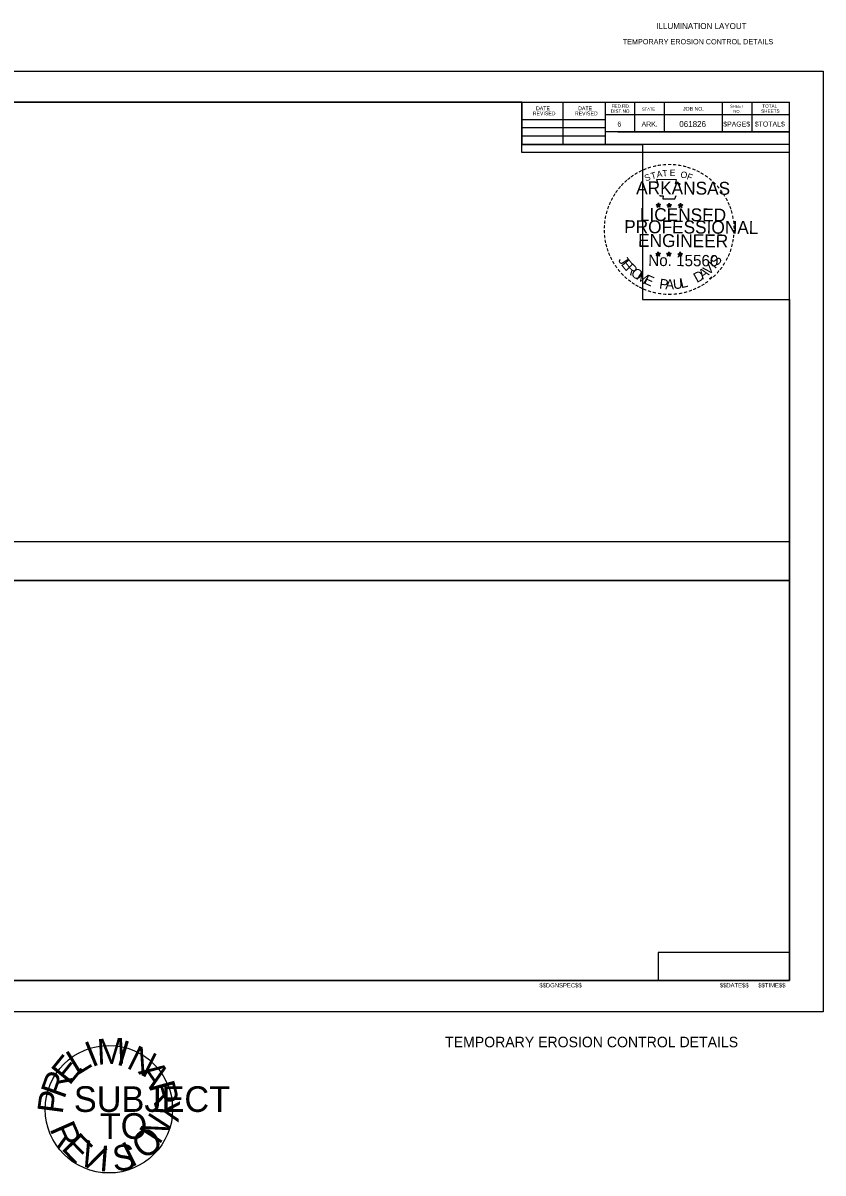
# Model space of a CAD drawing. Extents: x -1.6 to 32.4, y -4.5 to 22.4.
# Drawn here: x 13.68 to 32.4, y -4.5 to 22.4 of the extents above; entities that cross this region are included whole.
import ezdxf

# ---------------------------------------------------------------- set-up
doc = ezdxf.new("R2010")
doc.units = 0
for name, color, linetype in [('Level 1', 7, 'Continuous'), ('Level 37', 7, 'Continuous'), ('Level 48', 7, 'Continuous'), ('Level 49', 7, 'Continuous'), ('Level 63', 7, 'Continuous'), ('R_Border Prelim', 7, 'Continuous'), ('R_No Plot', 7, 'Continuous'), ('TYPICAL FONT', 7, 'Continuous')]:
    doc.layers.add(name, color=color, linetype=linetype)

# ---------------------------------------------------------------- blocks, each defined once
blk = doc.blocks.new('JDAVISAR')
at = {"layer": 'Level 49'}
for p, q in [((-0.129, 0.302), (-0.133, 0.28)), ((-0.129, 0.302), (-0.133, 0.282)), ((-0.129, 0.302), (-0.131, 0.282)), ((-0.129, 0.271), (-0.129, 0.302)), ((-0.129, 0.302), (-0.124, 0.28)), ((-0.129, 0.302), (-0.125, 0.282)), ((-0.129, 0.302), (-0.128, 0.282)), ((0.006, 0.3), (0.002, 0.279)), ((0.006, 0.3), (0.002, 0.28)), ((0.006, 0.3), (0.003, 0.28)), ((0.006, 0.271), (0.006, 0.3)), ((0.006, 0.3), (0.011, 0.279)), ((0.006, 0.3), (0.01, 0.28)), ((0.006, 0.3), (0.007, 0.28)), ((0.149, 0.298), (0.144, 0.279)), ((0.149, 0.298), (0.147, 0.278)), ((0.149, 0.298), (0.147, 0.278)), ((0.149, 0.268), (0.149, 0.298)), ((0.149, 0.298), (0.155, 0.278)), ((0.149, 0.298), (0.153, 0.278)), ((0.149, 0.298), (0.151, 0.278)), ((-0.158, 0.28), (-0.129, 0.271)), ((-0.158, 0.28), (-0.137, 0.279)), ((-0.158, 0.28), (-0.137, 0.278)), ((-0.158, 0.28), (-0.139, 0.275)), ((-0.158, 0.28), (-0.139, 0.272)), ((-0.158, 0.28), (-0.139, 0.271)), ((-0.158, 0.28), (-0.139, 0.268)), ((-0.146, 0.247), (-0.129, 0.271)), ((-0.146, 0.247), (-0.139, 0.27)), ((-0.146, 0.247), (-0.137, 0.267)), ((-0.146, 0.247), (-0.136, 0.266)), ((-0.146, 0.247), (-0.133, 0.264)), ((-0.146, 0.247), (-0.129, 0.264)), ((-0.146, 0.247), (-0.129, 0.262)), ((-0.101, 0.28), (-0.129, 0.271)), ((-0.112, 0.246), (-0.129, 0.271)), ((-0.112, 0.246), (-0.129, 0.264)), ((-0.112, 0.246), (-0.129, 0.262)), ((-0.101, 0.28), (-0.127, 0.278)), ((-0.112, 0.246), (-0.127, 0.264)), ((-0.101, 0.28), (-0.124, 0.276)), ((-0.101, 0.28), (-0.124, 0.274)), ((-0.112, 0.246), (-0.124, 0.27)), ((-0.112, 0.246), (-0.124, 0.267)), ((-0.112, 0.246), (-0.121, 0.271)), ((-0.101, 0.28), (-0.12, 0.274)), ((-0.101, 0.28), (-0.117, 0.272)), ((-0.101, 0.28), (-0.116, 0.271)), ((-0.023, 0.279), (0.006, 0.271)), ((-0.023, 0.279), (-0.002, 0.278)), ((-0.023, 0.279), (-0.002, 0.276)), ((-0.023, 0.279), (-0.002, 0.275)), ((-0.023, 0.279), (-0.003, 0.271)), ((-0.023, 0.279), (-0.003, 0.27)), ((-0.023, 0.279), (-0.003, 0.267)), ((-0.011, 0.246), (0.006, 0.271)), ((-0.011, 0.246), (-0.002, 0.268)), ((-0.011, 0.246), (-0.002, 0.267)), ((-0.011, 0.246), (-0.001, 0.266)), ((-0.011, 0.246), (0.002, 0.263)), ((-0.011, 0.246), (0.006, 0.263)), ((-0.011, 0.246), (0.006, 0.262)), ((0.034, 0.279), (0.006, 0.271)), ((0.023, 0.246), (0.006, 0.271)), ((0.023, 0.246), (0.006, 0.263)), ((0.023, 0.246), (0.006, 0.262)), ((0.034, 0.279), (0.009, 0.278)), ((0.023, 0.246), (0.009, 0.263)), ((0.034, 0.279), (0.011, 0.275)), ((0.034, 0.279), (0.011, 0.274)), ((0.023, 0.246), (0.011, 0.27)), ((0.023, 0.246), (0.011, 0.266)), ((0.023, 0.246), (0.014, 0.27)), ((0.034, 0.279), (0.015, 0.272)), ((0.034, 0.279), (0.018, 0.271)), ((0.034, 0.279), (0.019, 0.27)), ((0.12, 0.278), (0.149, 0.268)), ((0.12, 0.278), (0.143, 0.275)), ((0.12, 0.278), (0.141, 0.274)), ((0.12, 0.278), (0.141, 0.272)), ((0.12, 0.278), (0.14, 0.27)), ((0.12, 0.278), (0.14, 0.267)), ((0.12, 0.278), (0.14, 0.267)), ((0.131, 0.245), (0.149, 0.268)), ((0.131, 0.245), (0.141, 0.267)), ((0.131, 0.245), (0.143, 0.264)), ((0.131, 0.245), (0.143, 0.263)), ((0.131, 0.245), (0.149, 0.263)), ((0.131, 0.245), (0.147, 0.262)), ((0.131, 0.245), (0.151, 0.259)), ((0.177, 0.278), (0.149, 0.268)), ((0.165, 0.245), (0.149, 0.268)), ((0.165, 0.245), (0.149, 0.263)), ((0.165, 0.245), (0.149, 0.259)), ((0.177, 0.278), (0.152, 0.275)), ((0.165, 0.245), (0.152, 0.262)), ((0.177, 0.278), (0.155, 0.274)), ((0.177, 0.278), (0.155, 0.271)), ((0.165, 0.245), (0.155, 0.267)), ((0.165, 0.245), (0.155, 0.264)), ((0.165, 0.245), (0.157, 0.267)), ((0.177, 0.278), (0.159, 0.27)), ((0.177, 0.278), (0.16, 0.27)), ((0.177, 0.278), (0.163, 0.268)), ((-0.162, -0.334), (-0.133, -0.343)), ((-0.162, -0.334), (-0.141, -0.335)), ((-0.162, -0.334), (-0.142, -0.338)), ((-0.162, -0.334), (-0.142, -0.338)), ((-0.162, -0.334), (-0.142, -0.342)), ((-0.162, -0.334), (-0.142, -0.343)), ((-0.162, -0.334), (-0.142, -0.344)), ((-0.152, -0.365), (-0.133, -0.343)), ((-0.152, -0.365), (-0.142, -0.343)), ((-0.152, -0.365), (-0.141, -0.347)), ((-0.152, -0.365), (-0.14, -0.347)), ((-0.152, -0.365), (-0.133, -0.348)), ((-0.152, -0.365), (-0.137, -0.35)), ((-0.152, -0.365), (-0.133, -0.351)), ((-0.133, -0.312), (-0.139, -0.332)), ((-0.133, -0.312), (-0.137, -0.334)), ((-0.133, -0.312), (-0.136, -0.334)), ((-0.117, -0.367), (-0.135, -0.351)), ((-0.133, -0.343), (-0.133, -0.312)), ((-0.133, -0.312), (-0.129, -0.334)), ((-0.133, -0.312), (-0.129, -0.334)), ((-0.133, -0.312), (-0.133, -0.334)), ((-0.105, -0.334), (-0.133, -0.343)), ((-0.117, -0.367), (-0.133, -0.343)), ((-0.117, -0.367), (-0.133, -0.35)), ((-0.117, -0.367), (-0.132, -0.35)), ((-0.105, -0.334), (-0.131, -0.335)), ((-0.105, -0.334), (-0.129, -0.338)), ((-0.105, -0.334), (-0.129, -0.339)), ((-0.117, -0.367), (-0.129, -0.343)), ((-0.117, -0.367), (-0.129, -0.347)), ((-0.105, -0.334), (-0.125, -0.34)), ((-0.117, -0.367), (-0.125, -0.343)), ((-0.105, -0.334), (-0.123, -0.342)), ((-0.105, -0.334), (-0.121, -0.343)), ((-0.027, -0.334), (0.002, -0.343)), ((-0.027, -0.334), (-0.006, -0.336)), ((-0.027, -0.334), (-0.006, -0.338)), ((-0.027, -0.334), (-0.006, -0.339)), ((-0.027, -0.334), (-0.007, -0.342)), ((-0.027, -0.334), (-0.007, -0.344)), ((-0.027, -0.334), (-0.007, -0.346)), ((-0.017, -0.367), (0.002, -0.343)), ((-0.017, -0.367), (-0.006, -0.344)), ((-0.017, -0.367), (-0.006, -0.348)), ((-0.017, -0.367), (-0.005, -0.348)), ((-0.017, -0.367), (-0.002, -0.35)), ((-0.017, -0.367), (0.002, -0.35)), ((-0.017, -0.367), (0.002, -0.352)), ((0.002, -0.314), (-0.003, -0.334)), ((0.002, -0.314), (-0.002, -0.334)), ((0.002, -0.314), (-0.001, -0.334)), ((0.018, -0.367), (0.001, -0.352)), ((0.002, -0.343), (0.002, -0.314)), ((0.002, -0.314), (0.006, -0.335)), ((0.002, -0.314), (0.006, -0.335)), ((0.002, -0.314), (0.002, -0.334)), ((0.029, -0.335), (0.002, -0.343)), ((0.018, -0.367), (0.002, -0.343)), ((0.018, -0.367), (0.002, -0.35)), ((0.018, -0.367), (0.003, -0.35)), ((0.029, -0.335), (0.005, -0.335)), ((0.029, -0.335), (0.006, -0.339)), ((0.029, -0.335), (0.006, -0.339)), ((0.018, -0.367), (0.006, -0.344)), ((0.018, -0.367), (0.006, -0.347)), ((0.029, -0.335), (0.01, -0.342)), ((0.018, -0.367), (0.01, -0.344)), ((0.029, -0.335), (0.013, -0.343)), ((0.029, -0.335), (0.014, -0.344)), ((0.116, -0.336), (0.145, -0.346)), ((0.116, -0.336), (0.137, -0.338)), ((0.116, -0.336), (0.137, -0.34)), ((0.116, -0.336), (0.136, -0.342)), ((0.116, -0.336), (0.136, -0.344)), ((0.116, -0.336), (0.135, -0.346)), ((0.116, -0.336), (0.135, -0.348)), ((0.127, -0.369), (0.145, -0.346)), ((0.127, -0.369), (0.136, -0.346)), ((0.127, -0.369), (0.137, -0.35)), ((0.127, -0.369), (0.139, -0.35)), ((0.127, -0.369), (0.141, -0.352)), ((0.127, -0.369), (0.144, -0.352)), ((0.127, -0.369), (0.145, -0.354)), ((0.145, -0.315), (0.14, -0.336)), ((0.145, -0.315), (0.141, -0.336)), ((0.145, -0.315), (0.143, -0.336)), ((0.161, -0.369), (0.144, -0.352)), ((0.161, -0.369), (0.144, -0.354)), ((0.145, -0.346), (0.145, -0.315)), ((0.145, -0.315), (0.149, -0.336)), ((0.145, -0.315), (0.149, -0.336)), ((0.145, -0.315), (0.145, -0.336)), ((0.173, -0.336), (0.145, -0.346)), ((0.161, -0.369), (0.145, -0.346)), ((0.161, -0.369), (0.147, -0.352)), ((0.173, -0.336), (0.148, -0.338)), ((0.173, -0.336), (0.149, -0.34)), ((0.173, -0.336), (0.149, -0.342)), ((0.161, -0.369), (0.149, -0.35)), ((0.161, -0.369), (0.151, -0.346)), ((0.161, -0.369), (0.152, -0.346)), ((0.173, -0.336), (0.155, -0.343)), ((0.173, -0.336), (0.156, -0.346)), ((0.173, -0.336), (0.157, -0.346))]:
    blk.add_line(p, q, dxfattribs=at)
for points in [[(-0.152, 0.595), (-0.132, 0.527)], [(0.132, 0.518), (0.144, 0.542), (0.087, 0.539), (0.1, 0.593), (-0.152, 0.595)], [(-0.129, 0.302), (-0.112, 0.246), (-0.158, 0.28), (-0.101, 0.28), (-0.146, 0.247), (-0.129, 0.302)], [(-0.113, 0.398), (-0.113, 0.39), (-0.068, 0.389), (-0.072, 0.352), (0.079, 0.351), (0.095, 0.393)], [(0.006, 0.3), (0.023, 0.246), (-0.023, 0.279), (0.034, 0.279), (-0.011, 0.246), (0.006, 0.3)], [(0.149, 0.298), (0.165, 0.245), (0.12, 0.278), (0.177, 0.278), (0.131, 0.245), (0.149, 0.298)], [(-0.133, -0.312), (-0.117, -0.367), (-0.162, -0.334), (-0.105, -0.334), (-0.152, -0.365), (-0.133, -0.312)], [(0.002, -0.314), (0.018, -0.367), (-0.027, -0.334), (0.029, -0.335), (-0.017, -0.367), (0.002, -0.314)], [(0.145, -0.315), (0.161, -0.369), (0.116, -0.336), (0.173, -0.336), (0.127, -0.369), (0.145, -0.315)], [(0.52, -0.661), (0.516, -0.648), (0.54, -0.628)], [(0.538, -0.625), (0.542, -0.637), (0.518, -0.658)], [(0.542, -0.635), (0.518, -0.656)], [(0.542, -0.637), (0.519, -0.657)]]:
    blk.add_lwpolyline(points, dxfattribs=at)
for centre, radius in [((-0.128, 0.27), 0.014), ((-0.128, 0.27), 0.0126), ((-0.128, 0.27), 0.0117), ((-0.128, 0.27), 0.0108), ((-0.128, 0.27), 0.00938), ((-0.128, 0.27), 0.00871), ((-0.128, 0.27), 0.00803), ((-0.128, 0.27), 0.00691), ((-0.128, 0.27), 0.00605), ((-0.128, 0.27), 0.00503), ((-0.128, 0.27), 0.00401), ((-0.128, 0.27), 0.00299), ((-0.128, 0.27), 0.0024), ((-0.128, 0.27), 0.00117), ((0.007, 0.269), 0.014), ((0.007, 0.269), 0.0126), ((0.007, 0.269), 0.0117), ((0.007, 0.269), 0.0108), ((0.007, 0.269), 0.00938), ((0.007, 0.269), 0.00871), ((0.007, 0.269), 0.00803), ((0.007, 0.269), 0.00691), ((0.007, 0.269), 0.00605), ((0.007, 0.269), 0.00503), ((0.007, 0.269), 0.00401), ((0.007, 0.269), 0.00299), ((0.007, 0.269), 0.0024), ((0.007, 0.269), 0.00117), ((0.15, 0.267), 0.014), ((0.15, 0.267), 0.0126), ((0.15, 0.267), 0.0117), ((0.15, 0.267), 0.0108), ((0.15, 0.267), 0.00938), ((0.15, 0.267), 0.00803), ((0.15, 0.267), 0.00871), ((0.15, 0.267), 0.00691), ((0.15, 0.267), 0.00605), ((0.15, 0.267), 0.00503), ((0.15, 0.267), 0.00401), ((0.15, 0.267), 0.00299), ((0.15, 0.267), 0.0024), ((0.15, 0.267), 0.00117), ((-0.133, -0.343), 0.014), ((-0.133, -0.343), 0.0126), ((-0.133, -0.343), 0.0117), ((-0.133, -0.343), 0.0108), ((-0.133, -0.343), 0.00938), ((-0.133, -0.343), 0.00871), ((-0.133, -0.343), 0.00803), ((-0.133, -0.343), 0.00691), ((-0.133, -0.343), 0.00605), ((-0.133, -0.343), 0.00503), ((-0.133, -0.343), 0.00401), ((-0.133, -0.343), 0.00299), ((-0.133, -0.343), 0.0024), ((-0.133, -0.343), 0.00117), ((0.003, -0.344), 0.014), ((0.003, -0.344), 0.0126), ((0.003, -0.344), 0.0117), ((0.003, -0.344), 0.0108), ((0.003, -0.344), 0.00938), ((0.003, -0.344), 0.00871), ((0.003, -0.344), 0.00803), ((0.003, -0.344), 0.00691), ((0.003, -0.344), 0.00605), ((0.003, -0.344), 0.00503), ((0.003, -0.344), 0.00401), ((0.003, -0.344), 0.00299), ((0.003, -0.344), 0.0024), ((0.003, -0.344), 0.00117), ((0.146, -0.346), 0.014), ((0.146, -0.346), 0.0126), ((0.146, -0.346), 0.0117), ((0.146, -0.346), 0.0108), ((0.146, -0.346), 0.00938), ((0.146, -0.346), 0.00871), ((0.146, -0.346), 0.00803), ((0.146, -0.346), 0.00691), ((0.146, -0.346), 0.00605), ((0.146, -0.346), 0.00503), ((0.146, -0.346), 0.00401), ((0.146, -0.346), 0.00299), ((0.146, -0.346), 0.0024), ((0.146, -0.346), 0.00117)]:
    blk.add_circle(centre, radius, dxfattribs=at)
for s, height, rotation, p in [('-', 0.13, 23.9096, (-0.306, 0.666)), ('-', 0.13, 18.7785, (-0.254, 0.688)), ('-', 0.13, 13.2326, (-0.193, 0.707)), ('-', 0.13, 9.8217, (-0.139, 0.72)), ('-', 0.13, 5.4992, (-0.079, 0.728)), ('-', 0.13, 359.7886, (-0.017, 0.734)), ('-', 0.13, 357.3454, (0.043, 0.732)), ('-', 0.13, 351.7641, (0.102, 0.727)), ('-', 0.13, 346.8073, (0.161, 0.718)), ('-', 0.13, 341.9386, (0.212, 0.704)), ('-', 0.13, 337.4575, (0.271, 0.686)), ('-', 0.13, 42.5646, (-0.527, 0.516)), ('-', 0.13, 38.5531, (-0.491, 0.549)), ('-', 0.13, 35.8341, (-0.453, 0.58)), ('-', 0.13, 33.666, (-0.406, 0.612)), ('-', 0.13, 28.3942, (-0.357, 0.641)), ('S', 0.081, 21.1964, (-0.287, 0.57)), ('T', 0.081, 16.006, (-0.213, 0.597)), ('A', 0.081, 10.8156, (-0.145, 0.617)), ('T', 0.081, 5.6252, (-0.076, 0.63)), ('E', 0.081, 0.4347, (0.013, 0.638)), ('O', 0.081, 350.0539, (0.143, 0.621)), ('F', 0.081, 339.6731, (0.22, 0.601)), ('-', 0.13, 333.7235, (0.323, 0.665)), ('-', 0.13, 329.2433, (0.369, 0.641)), ('-', 0.13, 325.4651, (0.421, 0.61)), ('-', 0.13, 320.1321, (0.47, 0.576)), ('-', 0.13, 53.8349, (-0.631, 0.393)), ('-', 0.13, 50.2166, (-0.597, 0.439)), ('-', 0.13, 48.0254, (-0.564, 0.478)), ('ARKANSAS', 0.162, 359.6024, (-0.409, 0.411)), ('-', 0.13, 315.181, (0.519, 0.536)), ('-', 0.13, 309.4821, (0.564, 0.491)), ('-', 0.13, 306.2546, (0.605, 0.442)), ('-', 0.13, 67.3767, (-0.703, 0.251)), ('-', 0.13, 62.4738, (-0.682, 0.3)), ('-', 0.13, 57.673, (-0.657, 0.349)), ('-', 0.113, 303.2777, (0.645, 0.395)), ('-', 0.13, 299.2708, (0.67, 0.346)), ('-', 0.13, 294.2652, (0.696, 0.296)), ('-', 0.13, 75.0634, (-0.738, 0.142)), ('-', 0.13, 71.9969, (-0.722, 0.2)), ('LICENSED', 0.162, 359.6024, (-0.363, 0.075)), ('-', 0.13, 290.1752, (0.718, 0.251)), ('-', 0.13, 284.7257, (0.735, 0.203)), ('-', 0.13, 280.1517, (0.751, 0.142)), ('-', 0.13, 88.6646, (-0.758, -0.028)), ('-', 0.13, 84.7887, (-0.756, 0.029)), ('-', 0.13, 80.8037, (-0.75, 0.085)), ('PROFESSIONAL', 0.16204, 359.6024, (-0.56, -0.077)), ('-', 0.13, 276.1986, (0.765, 0.08)), ('-', 0.13, 273.9325, (0.769, 0.021)), ('-', 0.13, 93.7983, (-0.756, -0.087)), ('-', 0.13, 98.5503, (-0.75, -0.142)), ('ENGINEER', 0.162, 359.6024, (-0.385, -0.25)), ('-', 0.13, 263.1196, (0.769, -0.083)), ('-', 0.13, 269.5431, (0.771, -0.029)), ('-', 0.13, 101.3173, (-0.741, -0.201)), ('-', 0.13, 105.0602, (-0.727, -0.249)), ('-', 0.13, 108.6898, (-0.71, -0.299)), ('-', 0.13, 252.4705, (0.739, -0.25)), ('-', 0.13, 255.365, (0.753, -0.191)), ('-', 0.13, 260.5977, (0.762, -0.136)), ('-', 0.13, 113.6667, (-0.69, -0.349)), ('-', 0.13, 115.3313, (-0.665, -0.399)), ('-', 0.13, 120.0495, (-0.637, -0.447)), ('J', 0.125, 303.9209, (-0.64, -0.418)), ('E', 0.125, 308.618, (-0.605, -0.471)), ('No. 15560', 0.1426, 359.6024, (-0.257, -0.49)), ('I', 0.125, 49.9999, (0.582, -0.534)), ('S', 0.125, 53.5227, (0.612, -0.498)), ('-', 0.13, 244.2221, (0.698, -0.355)), ('-', 0.13, 247.4911, (0.721, -0.305)), ('-', 0.13, 125.4958, (-0.604, -0.492)), ('-', 0.13, 130.3205, (-0.568, -0.537)), ('-', 0.13, 133.8262, (-0.526, -0.581)), ('R', 0.125, 314.7784, (-0.552, -0.534)), ('O', 0.125, 321.6761, (-0.486, -0.599)), ('M', 0.125, 328.1357, (-0.417, -0.651)), ('D', 0.125, 28.5809, (0.354, -0.705)), ('A', 0.125, 34.8903, (0.427, -0.664)), ('V', 0.125, 41.4844, (0.499, -0.612)), ('-', 0.13, 233.4476, (0.597, -0.512)), ('-', 0.13, 233.4476, (0.635, -0.468)), ('-', 0.13, 238.6736, (0.666, -0.415)), ('-', 0.13, 138.5362, (-0.485, -0.619)), ('-', 0.13, 144.2487, (-0.438, -0.652)), ('-', 0.13, 147.6922, (-0.394, -0.683)), ('E', 0.125, 336.4966, (-0.321, -0.707)), ('P', 0.125, 351.9783, (-0.124, -0.772)), ('A', 0.125, 357.9896, (-0.044, -0.782)), ('U', 0.125, 5.7635, (0.06, -0.783)), ('L', 0.125, 13.0992, (0.158, -0.771)), ('-', 0.13, 211.8515, (0.428, -0.669)), ('-', 0.13, 215.3387, (0.471, -0.638)), ('-', 0.13, 225.3677, (0.559, -0.559)), ('-', 0.13, 151.1728, (-0.348, -0.709)), ('-', 0.13, 154.2026, (-0.304, -0.73)), ('-', 0.13, 158.1636, (-0.254, -0.752)), ('-', 0.13, 162.4007, (-0.198, -0.769)), ('-', 0.13, 167.1579, (-0.141, -0.782)), ('-', 0.13, 172.7179, (-0.079, -0.791)), ('-', 0.13, 176.1207, (-0.018, -0.797)), ('-', 0.13, 181.1942, (0.042, -0.795)), ('-', 0.13, 185.4191, (0.108, -0.79)), ('-', 0.13, 190.8882, (0.168, -0.78)), ('-', 0.13, 195.0767, (0.227, -0.764)), ('-', 0.13, 200.3208, (0.282, -0.744)), ('-', 0.13, 203.854, (0.332, -0.722)), ('-', 0.13, 206.9592, (0.383, -0.697))]:
    blk.add_text(s, height=height, rotation=rotation, dxfattribs=at).set_placement(p)

msp = doc.modelspace()

# ---------------------------------------------------------------- linework, layer by layer
at = {"layer": 'Level 1'}
for p, q in [((-0.001, 20.545), (31.617, 20.545)), ((25.353, 19.557), (25.353, 20.545)), ((26.321, 19.557), (26.321, 20.545)), ((27.307, 20.545), (27.307, 19.557)), ((27.991, 20.545), (27.991, 19.851)), ((28.685, 20.545), (28.685, 19.851)), ((30.043, 20.545), (30.043, 19.851)), ((30.737, 20.545), (30.737, 19.851)), ((31.617, -0.001), (31.617, 20.545)), ((31.617, 20.251), (27.307, 20.251)), ((31.617, 20.253), (31.617, 20.253)), ((25.353, 20.143), (27.307, 20.143)), ((25.353, 19.957), (27.307, 19.957)), ((25.353, 19.763), (27.307, 19.763)), ((31.617, 19.851), (27.307, 19.851)), ((27.603, 19.851), (31.617, 19.851)), ((31.617, 19.557), (25.353, 19.557)), ((31.617, -0.001), (-0.001, -0.001))]:
    msp.add_line(p, q, dxfattribs=at)
at = {"layer": 'Level 37'}
for p, q in [((-0.001, 10.271), (31.617, 10.271)), ((31.617, 10.271), (31.617, -0.001)), ((31.617, -0.001), (-0.001, -0.001))]:
    msp.add_line(p, q, dxfattribs=at)
for points in [[(-0.001, 20.545), (25.353, 20.545), (25.353, 19.557), (28.175, 19.557), (28.175, 15.933), (31.617, 15.933), (31.617, 9.363), (-0.001, 9.363)], [(-0.001, 9.363), (31.617, 9.363), (31.617, 0.657), (28.548, 0.657), (28.546, 0), (-0.001, -0.001)]]:
    msp.add_lwpolyline(points, close=True, dxfattribs=at)
at = {"layer": 'Level 63'}
msp.add_lwpolyline([(-1.598, 21.273), (32.402, 21.273), (32.402, -0.727), (-1.598, -0.727)], close=True, dxfattribs=at)
at = {"layer": 'R_Border Prelim'}
msp.add_circle((15.691, -3.008), 1.492, dxfattribs=at)
at = {"layer": 'R_No Plot'}
for p, q in [((25.353, 19.374), (25.353, 20.545)), ((31.617, 19.374), (25.353, 19.374)), ((25.353, 19.374), (25.353, 19.374)), ((25.353, 19.374), (25.353, 19.374)), ((31.617, 19.374), (31.617, 19.374)), ((-0.001, -0.001), (31.617, -0.001)), ((31.617, -0.001), (31.617, -0.001))]:
    msp.add_line(p, q, dxfattribs=at)
for points in [[(25.353, 20.545), (25.353, 20.545), (25.353, 20.545), (-0.001, 20.545)], [(31.617, -0.001), (31.617, 19.374)]]:
    msp.add_lwpolyline(points, dxfattribs=at)

# ---------------------------------------------------------------- block references
at = {"layer": 'R_Border Prelim', "xscale": 1.8630626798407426, "yscale": 1.8630626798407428}
msp.add_blockref('JDAVISAR', (28.791, 17.63), dxfattribs=at)

# ---------------------------------------------------------------- texts
at = {"layer": 'Level 1'}
for s, height, p in [('ILLUMINATION LAYOUT', 0.14, (28.501, 22.258)), ('DATE', 0.0879, (25.687, 20.359)), ('DATE', 0.0879, (26.673, 20.359)), ('FED.RD.', 0.0782, (27.455, 20.417)), ('SHEET', 0.0684, (30.229, 20.417)), ('TOTAL', 0.0782, (30.981, 20.417)), ('REVISED', 0.0879, (25.609, 20.241)), ('REVISED', 0.0879, (26.595, 20.241)), ('DIST.NO.', 0.0782, (27.435, 20.299)), ('STATE', 0.0684, (28.167, 20.349)), ('JOB NO.', 0.0879, (29.125, 20.349)), ('NO.', 0.0684, (30.307, 20.299)), ('SHEETS', 0.0782, (30.953, 20.299)), ('6', 0.117, (27.591, 19.977)), ('ARK.', 0.1172, (28.157, 19.977)), ('061826', 0.14, (29.039, 19.966)), ('$PAGE$', 0.1172, (30.067, 19.977)), ('$TOTAL$', 0.1172, (30.806, 19.977))]:
    msp.add_text(s, height=height, dxfattribs=at).set_placement(p)
at = {"layer": 'Level 48'}
for s, p in [('$$DGNSPEC$$', (25.764, -0.159)), ('$$DATE$$', (29.986, -0.159)), ('$$TIME$$', (30.887, -0.159))]:
    msp.add_text(s, height=0.1, dxfattribs=at).set_placement(p)
at = {"layer": 'R_Border Prelim'}
for s, rotation, p in [('M', 2.6943, (15.423, -1.967)), ('I', 22.0105, (15.291, -2.033)), ('I', 343.3781, (15.843, -1.955)), ('N', 333.7199, (16.08, -2.031)), ('E', 50.9849, (14.766, -2.471)), ('L', 31.6686, (14.943, -2.229)), ('R', 70.3011, (14.646, -2.787)), ('A', 304.7456, (16.362, -2.135)), ('R', 285.4294, (16.623, -2.439)), ('P', 82.6089, (14.607, -3.137)), ('Y', 266.1131, (16.758, -2.763)), ('N', 57.1378, (16.872, -3.855)), ('R', 293.7639, (14.295, -3.465)), ('O', 36.5754, (16.509, -4.211)), ('E', 314.3262, (14.553, -3.933)), ('V', 334.8885, (14.925, -4.259)), ('I', 355.4508, (15.453, -4.451)), ('S', 5.732, (15.801, -4.461)), ('I', 26.2943, (16.203, -4.379))]:
    msp.add_text(s, height=0.6, rotation=rotation, dxfattribs=at).set_placement(p)
for s, p in [('SUBJECT', (14.871, -3.071)), ('TO', (15.477, -3.701))]:
    msp.add_text(s, height=0.6, dxfattribs=at).set_placement(p)
at = {"layer": 'TYPICAL FONT'}
for height, p in [(0.1224, (27.716, 21.901)), (0.24609, (23.559, -1.559))]:
    msp.add_text('TEMPORARY EROSION CONTROL DETAILS', height=height, dxfattribs=at).set_placement(p)

doc.saveas('drawing.dxf')
